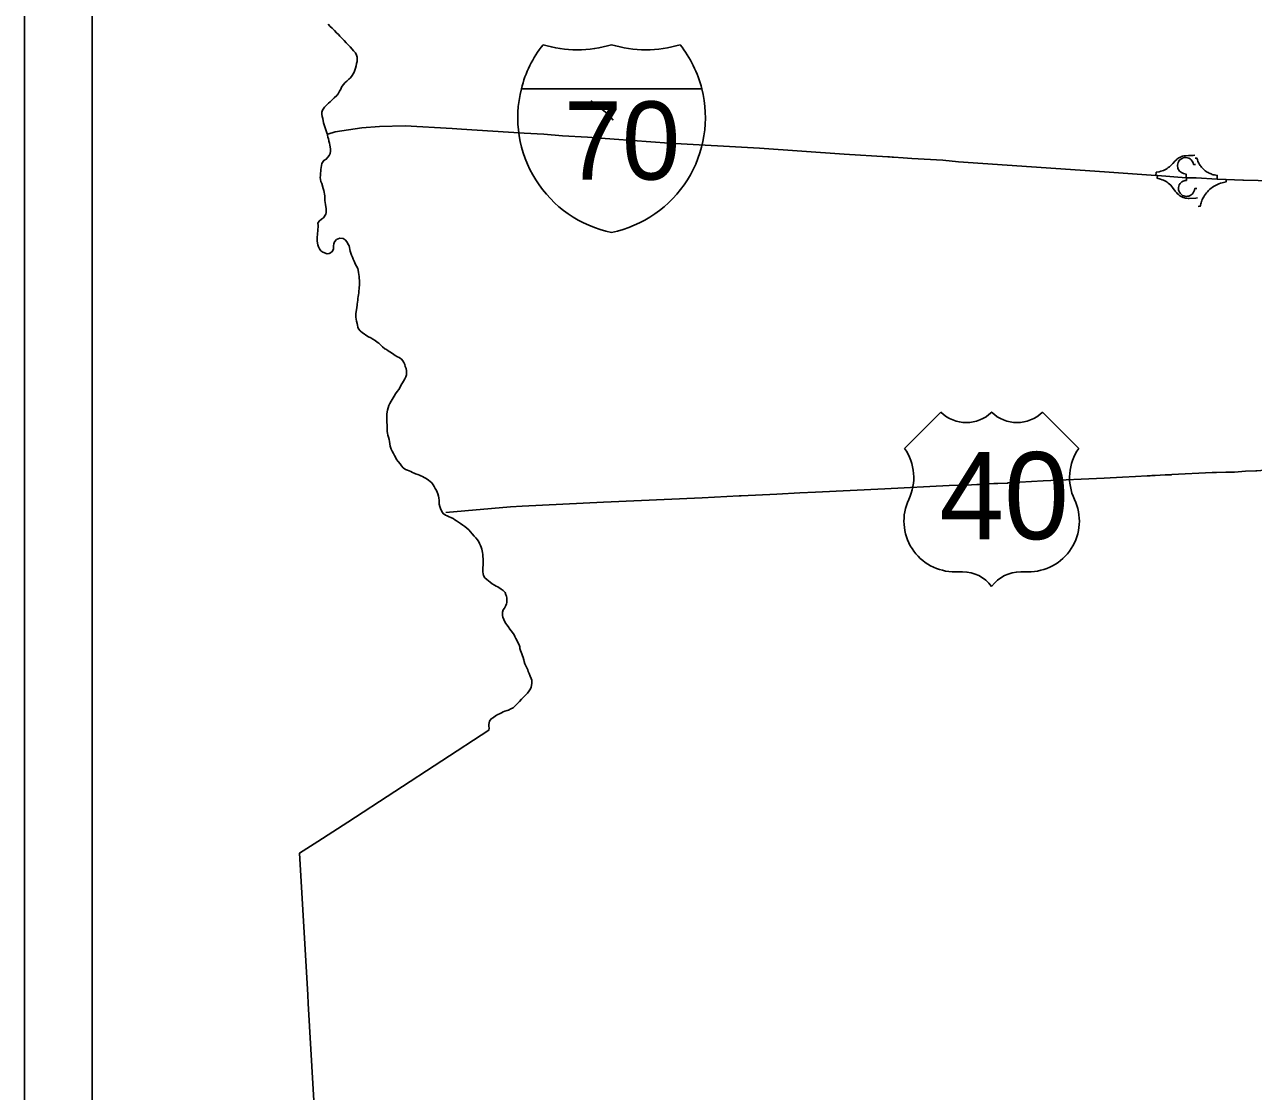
# Model space of a CAD drawing. Extents: x -7.1 to 34, y 0 to 22.
# Drawn here: x 2 to 3.818, y 16.034 to 17.612 of the extents above; entities that cross this region are included whole.
import ezdxf

# ---------------------------------------------------------------- set-up
doc = ezdxf.new("R2010")
doc.units = 0
for name, color, linetype in [('GM_X_County', 7, 'Continuous'), ('GM_X_County_Road', 7, 'Continuous'), ('GM_X_Interchange_Ramps', 7, 'Continuous'), ('GM_X_Interstate_Route', 7, 'Continuous'), ('GM_X_Interstate_Shield', 7, 'Continuous'), ('GM_X_US_Route', 7, 'Continuous'), ('GM_X_US_Shield', 7, 'Continuous'), ('SH_Data', 7, 'Continuous')]:
    doc.layers.add(name, color=color, linetype=linetype)

msp = doc.modelspace()

# ---------------------------------------------------------------- linework, layer by layer
at = {"layer": 'GM_X_County'}
msp.add_lwpolyline([(2.4304, 15.9776), (2.4197, 16.1634), (2.4189, 16.1766), (2.4068, 16.3861), (2.434, 16.4032), (2.478, 16.4318), (2.6868, 16.5679), (2.6875, 16.571), (2.687, 16.5738), (2.6869, 16.5762), (2.6873, 16.5787), (2.688, 16.5816), (2.6904, 16.5847), (2.6936, 16.5869), (2.6968, 16.589), (2.6999, 16.591), (2.7024, 16.5923), (2.7055, 16.5939), (2.7079, 16.5952), (2.7105, 16.596), (2.7137, 16.597), (2.716, 16.5978), (2.7195, 16.5994), (2.7228, 16.6013), (2.726, 16.6041), (2.7291, 16.6073), (2.7324, 16.6105), (2.7353, 16.6139), (2.7379, 16.6169), (2.7409, 16.6197), (2.7439, 16.623), (2.7466, 16.6263), (2.7485, 16.6293), (2.7494, 16.6316), (2.7501, 16.6342), (2.7504, 16.6374), (2.7506, 16.6398), (2.7503, 16.6422), (2.7495, 16.6447), (2.7479, 16.6479), (2.7467, 16.6517), (2.7452, 16.655), (2.7444, 16.6573), (2.7429, 16.6604), (2.7415, 16.6633), (2.7402, 16.666), (2.7392, 16.6694), (2.7386, 16.6722), (2.7377, 16.6754), (2.7366, 16.6779), (2.7356, 16.6808), (2.7344, 16.6836), (2.7336, 16.686), (2.7327, 16.6891), (2.7325, 16.6915), (2.7317, 16.6945), (2.7304, 16.697), (2.7288, 16.7001), (2.7268, 16.7039), (2.7255, 16.7064), (2.7241, 16.7092), (2.7217, 16.7125), (2.7199, 16.7151), (2.7181, 16.7175), (2.7152, 16.7213), (2.7135, 16.7237), (2.7119, 16.7261), (2.7104, 16.7285), (2.7089, 16.7317), (2.7077, 16.735), (2.7071, 16.7375), (2.7068, 16.7398), (2.707, 16.7427), (2.7082, 16.7462), (2.7099, 16.7487), (2.7121, 16.7524), (2.713, 16.7548), (2.7134, 16.7571), (2.7136, 16.7606), (2.7133, 16.7634), (2.7127, 16.7662), (2.7121, 16.7685), (2.7108, 16.7715), (2.708, 16.7746), (2.7051, 16.7767), (2.7002, 16.78), (2.6979, 16.7812), (2.695, 16.7828), (2.6919, 16.7847), (2.6887, 16.7869), (2.6862, 16.7888), (2.6839, 16.7908), (2.6811, 16.7936), (2.6789, 16.7967), (2.6782, 16.7995), (2.6779, 16.8024), (2.6779, 16.8054), (2.678, 16.8085), (2.6782, 16.8123), (2.6783, 16.8156), (2.6784, 16.8189), (2.6783, 16.8221), (2.678, 16.8245), (2.6777, 16.8279), (2.6774, 16.8309), (2.6763, 16.8357), (2.6754, 16.8386), (2.6745, 16.8411), (2.6729, 16.8444), (2.6718, 16.8467), (2.67, 16.8498), (2.6676, 16.8525), (2.6652, 16.8553), (2.662, 16.8584), (2.6597, 16.8616), (2.6572, 16.8644), (2.6543, 16.8671), (2.6512, 16.8692), (2.6481, 16.8713), (2.6448, 16.8737), (2.639, 16.8779), (2.6366, 16.8792), (2.6338, 16.881), (2.6306, 16.8827), (2.6281, 16.8839), (2.625, 16.8852), (2.6226, 16.8862), (2.6194, 16.8885), (2.6183, 16.8902), (2.6168, 16.8925), (2.6153, 16.8958), (2.6142, 16.899), (2.6134, 16.9026), (2.6132, 16.905), (2.6131, 16.908), (2.6129, 16.9117), (2.6124, 16.9141), (2.6114, 16.9175), (2.6105, 16.9202), (2.6093, 16.9225), (2.6076, 16.9255), (2.6059, 16.9286), (2.6047, 16.9309), (2.6023, 16.934), (2.5999, 16.9358), (2.5975, 16.9379), (2.5942, 16.9403), (2.591, 16.9421), (2.5886, 16.9433), (2.5863, 16.9444), (2.584, 16.9453), (2.5816, 16.9464), (2.5785, 16.9475), (2.5762, 16.9484), (2.5738, 16.9495), (2.5713, 16.9505), (2.5688, 16.9515), (2.5665, 16.9525), (2.5635, 16.9538), (2.5603, 16.9563), (2.5576, 16.959), (2.5554, 16.9621), (2.5527, 16.9653), (2.5504, 16.9686), (2.5487, 16.972), (2.5473, 16.9745), (2.546, 16.9772), (2.5437, 16.9808), (2.5422, 16.9839), (2.541, 16.9883), (2.5403, 16.9916), (2.5398, 16.9949), (2.5392, 16.9983), (2.5382, 17.0015), (2.5373, 17.0046), (2.5367, 17.0075), (2.5365, 17.0098), (2.5363, 17.0148), (2.5362, 17.0175), (2.5362, 17.02), (2.5359, 17.023), (2.5357, 17.0259), (2.5358, 17.0291), (2.5359, 17.0321), (2.5361, 17.0356), (2.5363, 17.0389), (2.5368, 17.0416), (2.5378, 17.0449), (2.5388, 17.0482), (2.5404, 17.0513), (2.5422, 17.0547), (2.5438, 17.0572), (2.5452, 17.0596), (2.5467, 17.0622), (2.5486, 17.0655), (2.5514, 17.0691), (2.5538, 17.0719), (2.5554, 17.0756), (2.5572, 17.0788), (2.559, 17.082), (2.5608, 17.0844), (2.5626, 17.0879), (2.5639, 17.0907), (2.5649, 17.094), (2.5651, 17.0968), (2.565, 17.0997), (2.5644, 17.1031), (2.5632, 17.1062), (2.5623, 17.1092), (2.5613, 17.1119), (2.5594, 17.1146), (2.5575, 17.1169), (2.5543, 17.1192), (2.5516, 17.1206), (2.5484, 17.1226), (2.5461, 17.124), (2.5429, 17.1261), (2.5405, 17.1278), (2.5378, 17.1295), (2.5353, 17.1312), (2.533, 17.1323), (2.5296, 17.1352), (2.5272, 17.1375), (2.524, 17.1404), (2.5216, 17.1422), (2.5186, 17.1445), (2.5153, 17.1463), (2.512, 17.1483), (2.5089, 17.1502), (2.505, 17.1523), (2.5022, 17.1543), (2.4999, 17.1558), (2.4965, 17.1588), (2.4941, 17.1619), (2.493, 17.1643), (2.4924, 17.1671), (2.4918, 17.1699), (2.4912, 17.1732), (2.4906, 17.1763), (2.4902, 17.1789), (2.4901, 17.1814), (2.4902, 17.184), (2.4906, 17.1873), (2.4911, 17.19), (2.4917, 17.1936), (2.492, 17.1966), (2.4922, 17.199), (2.4924, 17.2007), (2.4925, 17.2013), (2.4928, 17.204), (2.4932, 17.2065), (2.4936, 17.2095), (2.494, 17.2123), (2.4943, 17.2151), (2.4946, 17.2178), (2.495, 17.221), (2.4951, 17.2236), (2.4953, 17.226), (2.4954, 17.2285), (2.4956, 17.2309), (2.4955, 17.2336), (2.4952, 17.2365), (2.4949, 17.2392), (2.494, 17.2454), (2.4934, 17.2484), (2.4928, 17.2512), (2.4912, 17.2545), (2.4898, 17.257), (2.4887, 17.2594), (2.4875, 17.2618), (2.4863, 17.2648), (2.4852, 17.2678), (2.4838, 17.271), (2.4827, 17.2737), (2.4819, 17.2768), (2.4814, 17.2792), (2.4806, 17.2821), (2.48, 17.2845), (2.4784, 17.2878), (2.4771, 17.2901), (2.4741, 17.2935), (2.4712, 17.2956), (2.4663, 17.296), (2.4639, 17.2952), (2.4616, 17.2939), (2.4587, 17.2907), (2.4575, 17.2878), (2.457, 17.2844), (2.457, 17.282), (2.4569, 17.2796), (2.4552, 17.276), (2.4527, 17.2741), (2.4504, 17.2735), (2.4476, 17.273), (2.4413, 17.2752), (2.4384, 17.2773), (2.4361, 17.2803), (2.4347, 17.2833), (2.4336, 17.2862), (2.4333, 17.2888), (2.4328, 17.2921), (2.4328, 17.2946), (2.433, 17.2977), (2.4332, 17.3009), (2.4334, 17.3033), (2.4337, 17.3064), (2.434, 17.3096), (2.4343, 17.3119), (2.4345, 17.3148), (2.434, 17.318), (2.4359, 17.3213), (2.4391, 17.3241), (2.4422, 17.3261), (2.4456, 17.3316), (2.4461, 17.3341), (2.4461, 17.3366), (2.446, 17.3398), (2.4458, 17.3423), (2.4452, 17.3458), (2.4447, 17.3489), (2.4444, 17.3515), (2.4441, 17.3562), (2.444, 17.3585), (2.4438, 17.361), (2.4432, 17.3641), (2.4427, 17.3664), (2.4417, 17.3696), (2.4399, 17.3767), (2.4385, 17.3798), (2.4377, 17.3828), (2.4375, 17.3858), (2.4376, 17.3889), (2.4379, 17.392), (2.4382, 17.3951), (2.4385, 17.3974), (2.4388, 17.4004), (2.4391, 17.4035), (2.44, 17.4065), (2.4427, 17.4109), (2.4463, 17.4126), (2.4485, 17.4156), (2.4507, 17.4183), (2.452, 17.4213), (2.4525, 17.4246), (2.4525, 17.4278), (2.452, 17.4311), (2.4517, 17.4338), (2.4512, 17.4364), (2.4502, 17.4395), (2.45, 17.4405), (2.4494, 17.4429), (2.4488, 17.4456), (2.448, 17.4482), (2.4474, 17.4501), (2.4461, 17.4547), (2.445, 17.4575), (2.4443, 17.4606), (2.4433, 17.4636), (2.4423, 17.4664), (2.4413, 17.473), (2.4402, 17.476), (2.4399, 17.4792), (2.44, 17.4826), (2.4408, 17.4851), (2.4439, 17.4898), (2.4467, 17.4927), (2.4494, 17.4955), (2.4519, 17.4976), (2.4552, 17.5008), (2.458, 17.5036), (2.4617, 17.507), (2.4637, 17.5097), (2.466, 17.5133), (2.4677, 17.5164), (2.4689, 17.5195), (2.4711, 17.523), (2.4744, 17.5263), (2.4768, 17.5282), (2.4798, 17.531), (2.482, 17.5334), (2.4848, 17.5366), (2.4861, 17.539), (2.4874, 17.5414), (2.4886, 17.5445), (2.4895, 17.5474), (2.4906, 17.551), (2.4912, 17.5542), (2.4918, 17.5574), (2.4921, 17.5614), (2.4919, 17.5639), (2.4911, 17.5669), (2.4895, 17.5701), (2.4866, 17.573), (2.4847, 17.5755), (2.4815, 17.5788), (2.4786, 17.582), (2.4757, 17.5848), (2.4726, 17.5885), (2.4699, 17.5913), (2.4666, 17.5946), (2.4642, 17.5972), (2.4615, 17.5998), (2.4583, 17.6031), (2.4552, 17.6066), (2.4522, 17.6093), (2.4492, 17.6124)], dxfattribs=at)
at = {"layer": 'GM_X_County_Road'}
msp.add_lwpolyline([(2.8709, 17.4707), (2.8675, 17.4744), (2.8617, 17.4802), (2.8543, 17.4865), (2.8435, 17.495), (2.8377, 17.4993)], dxfattribs=at)
at = {"layer": 'GM_X_Interchange_Ramps'}
for points in [[(3.7313, 17.4186), (3.7287, 17.4184), (3.722, 17.4185), (3.7171, 17.418), (3.7152, 17.4176), (3.7131, 17.4171), (3.7116, 17.4166), (3.7101, 17.416), (3.7088, 17.4154), (3.7075, 17.4147), (3.7059, 17.4136), (3.7046, 17.4126), (3.7034, 17.4115), (3.7021, 17.4102), (3.6986, 17.4066), (3.6971, 17.4048), (3.6957, 17.4034), (3.6937, 17.4016), (3.692, 17.4003), (3.6904, 17.3992), (3.6886, 17.3981), (3.6869, 17.3971), (3.685, 17.3963), (3.6829, 17.3955), (3.6809, 17.3949), (3.6786, 17.3943), (3.6741, 17.3935), (3.6737, 17.3886)], [(3.7182, 17.3854), (3.7186, 17.3906), (3.7144, 17.3918), (3.7127, 17.3924), (3.7114, 17.393), (3.7099, 17.3941), (3.7087, 17.3952), (3.7077, 17.3965), (3.7069, 17.3977), (3.7063, 17.3992), (3.7059, 17.4007), (3.7056, 17.4024), (3.7056, 17.4041), (3.7059, 17.406), (3.7065, 17.4079), (3.7076, 17.4099), (3.7088, 17.4114), (3.7105, 17.4129), (3.7124, 17.414), (3.7139, 17.4146), (3.7158, 17.4151), (3.7182, 17.4152), (3.7204, 17.4148), (3.7225, 17.4141), (3.7243, 17.4131), (3.726, 17.4117), (3.7274, 17.4099), (3.7286, 17.4076), (3.7295, 17.4049), (3.732, 17.4051)], [(3.7641, 17.3834), (3.7644, 17.3887), (3.7601, 17.3895), (3.7584, 17.3899), (3.7569, 17.3903), (3.7553, 17.3909), (3.7538, 17.3915), (3.7526, 17.3921), (3.751, 17.3929), (3.7494, 17.3938), (3.7481, 17.3946), (3.7467, 17.3957), (3.7454, 17.3967), (3.7439, 17.398), (3.7426, 17.3993), (3.7412, 17.4009), (3.7401, 17.4024), (3.7391, 17.4037), (3.7382, 17.4051), (3.7372, 17.4069), (3.7364, 17.4085), (3.7358, 17.4099), (3.7351, 17.4117), (3.7342, 17.4144), (3.7315, 17.4143)], [(3.6759, 17.3885), (3.6757, 17.3846), (3.6803, 17.3834), (3.6827, 17.3825), (3.685, 17.3816), (3.6869, 17.3806), (3.6886, 17.3796), (3.6903, 17.3786), (3.6919, 17.3774), (3.6937, 17.376), (3.6955, 17.3743), (3.6969, 17.3727), (3.6983, 17.3711), (3.7024, 17.3656), (3.7039, 17.3635), (3.7053, 17.3619), (3.7069, 17.3604), (3.7084, 17.3591), (3.7101, 17.358), (3.712, 17.357), (3.714, 17.3561), (3.7158, 17.3555), (3.7175, 17.3552), (3.7191, 17.3549), (3.7212, 17.3547), (3.7231, 17.3547), (3.7328, 17.3553), (3.7351, 17.3554)], [(3.7341, 17.3696), (3.7313, 17.3695), (3.7306, 17.3672), (3.7299, 17.365), (3.7289, 17.3631), (3.7274, 17.3612), (3.7258, 17.3599), (3.7242, 17.359), (3.7225, 17.3583), (3.7205, 17.3579), (3.7183, 17.3578), (3.7164, 17.3581), (3.7148, 17.3585), (3.7131, 17.3593), (3.7118, 17.3602), (3.7104, 17.3614), (3.7094, 17.3627), (3.7084, 17.3642), (3.7077, 17.366), (3.7073, 17.3674), (3.7071, 17.369), (3.7072, 17.3708), (3.7075, 17.3727), (3.7083, 17.3747), (3.7094, 17.3766), (3.7106, 17.378), (3.7121, 17.3793), (3.714, 17.3804), (3.7155, 17.3809), (3.717, 17.3813), (3.7188, 17.3815), (3.7191, 17.3853)], [(3.7362, 17.343), (3.7392, 17.3432), (3.7396, 17.345), (3.7401, 17.3469), (3.7405, 17.3484), (3.7411, 17.35), (3.7417, 17.3514), (3.7423, 17.353), (3.7435, 17.3554), (3.7445, 17.3573), (3.7456, 17.359), (3.7469, 17.361), (3.7483, 17.3628), (3.75, 17.3647), (3.7517, 17.3665), (3.7536, 17.3684), (3.7552, 17.3697), (3.7571, 17.3711), (3.759, 17.3723), (3.7616, 17.3739), (3.7639, 17.3751), (3.7667, 17.3763), (3.7693, 17.3772), (3.7717, 17.3779), (3.7738, 17.3784), (3.7775, 17.3791), (3.7776, 17.3829)]]:
    msp.add_lwpolyline(points, dxfattribs=at)
at = {"layer": 'GM_X_Interstate_Route'}
for points in [[(2.4487, 17.45), (2.4596, 17.4532), (2.4987, 17.4592), (2.5253, 17.4614), (2.563, 17.4622), (2.6325, 17.4581), (2.6466, 17.457), (2.739, 17.4512), (2.768, 17.4498), (2.7959, 17.4476), (2.8327, 17.4455), (2.8723, 17.4424), (2.9535, 17.4366), (3.0873, 17.4293), (3.2127, 17.4203), (3.2773, 17.4163), (3.2797, 17.4161), (3.2833, 17.4159)], [(3.2833, 17.4159), (3.2857, 17.4157)], [(3.2857, 17.4157), (3.2997, 17.4149), (3.3127, 17.414)], [(3.3127, 17.414), (3.3583, 17.4112), (3.3817, 17.4088), (3.5976, 17.3939)], [(3.5976, 17.3939), (3.6737, 17.3886), (3.6759, 17.3885), (3.7182, 17.3854), (3.7191, 17.3853), (3.7323, 17.385)], [(3.7323, 17.385), (3.7332, 17.385), (3.7641, 17.3834), (3.7776, 17.3829), (3.8023, 17.3817)], [(3.8023, 17.3817), (3.8031, 17.3817), (3.8678, 17.3801), (3.8961, 17.3791)]]:
    msp.add_lwpolyline(points, dxfattribs=at)
at = {"layer": 'GM_X_Interstate_Shield'}
for p, q in [((2.7348, 17.5171), (3.0019, 17.5171)), ((3.0019, 17.5171), (2.7348, 17.5171)), ((3.0019, 17.5171), (2.7348, 17.5171))]:
    msp.add_line(p, q, dxfattribs=at)
for centre, start, end in [((2.9031, 17.4745), 141.669, 165.8066), ((2.8177, 17.7481), 253.0091, 286.9909), ((2.9191, 17.7481), 253.0091, 286.9909), ((2.8337, 17.4745), 14.1934, 38.331), ((2.9031, 17.4745), 165.8066, 258.463), ((2.8337, 17.4745), 281.537, 14.1934)]:
    msp.add_arc(centre, 0.1735, start, end, dxfattribs=at)
at = {"layer": 'GM_X_US_Route'}
for points in [[(3.624, 16.9424), (3.6434, 16.9433), (3.6605, 16.9442)], [(3.6605, 16.9442), (3.6654, 16.9445)], [(3.6654, 16.9445), (3.6678, 16.9446)], [(3.6678, 16.9446), (3.6714, 16.9448), (3.6727, 16.9448)], [(3.6727, 16.9448), (3.6873, 16.9456)], [(3.6873, 16.9456), (3.6965, 16.946), (3.6971, 16.9461)], [(3.6971, 16.9461), (3.7569, 16.9491), (3.7581, 16.9491)], [(3.7581, 16.9491), (3.7633, 16.9494), (3.777, 16.9496), (3.7777, 16.9496)], [(3.7777, 16.9496), (3.7801, 16.9497), (3.79, 16.95), (3.8062, 16.9512), (3.8217, 16.9517), (3.8228, 16.9518), (3.8288, 16.952), (3.8415, 16.9527), (3.846, 16.953), (3.8535, 16.9535), (3.8596, 16.9538), (3.8639, 16.954)], [(2.7359, 16.8995), (2.8563, 16.9056), (3.0025, 16.9119), (3.0569, 16.9149), (3.0602, 16.9149), (3.1127, 16.9174), (3.1467, 16.9191), (3.1701, 16.9202), (3.2727, 16.9252), (3.3677, 16.9299)], [(3.3677, 16.9299), (3.3932, 16.9305), (3.4011, 16.9311)], [(3.4011, 16.9311), (3.4086, 16.9315), (3.4124, 16.9317)], [(3.4124, 16.9317), (3.4172, 16.9319), (3.4258, 16.9323), (3.4337, 16.9328), (3.4396, 16.933), (3.4539, 16.9337), (3.4552, 16.9338)], [(3.4552, 16.9338), (3.507, 16.9368)], [(3.507, 16.9368), (3.5972, 16.9411)], [(3.5972, 16.9411), (3.624, 16.9424)], [(2.6231, 16.8903), (2.719, 16.8986), (2.7359, 16.8995)]]:
    msp.add_lwpolyline(points, dxfattribs=at)
at = {"layer": 'GM_X_US_Shield'}
for p, q in [((3.3555, 17.0385), (3.3018, 16.9848)), ((3.5595, 16.9848), (3.5058, 17.0385)), ((3.377, 16.8023), (3.3877, 16.8023)), ((3.4736, 16.8023), (3.4844, 16.8023))]:
    msp.add_line(p, q, dxfattribs=at)
for centre, radius, start, end in [((3.3931, 17.0769), 0.0537, 225.573, 314.427), ((3.4682, 17.0769), 0.0537, 225.573, 314.427), ((3.2402, 16.9417), 0.0752, 334.5471, 35.0009), ((3.6211, 16.9417), 0.0752, 144.9991, 205.4529), ((3.3761, 16.8775), 0.0752, 154.8319, 270.6383), ((3.4852, 16.8775), 0.0752, 269.3617, 25.1681), ((3.3877, 16.7486), 0.0537, 36.8699, 90), ((3.4736, 16.7486), 0.0537, 90, 143.1301)]:
    msp.add_arc(centre, radius, start, end, dxfattribs=at)
at = {"layer": 'SH_Data'}
for p, q in [((2, 21), (2, 14)), ((2.1, 20.9), (2.1, 14.1))]:
    msp.add_line(p, q, dxfattribs=at)

# ---------------------------------------------------------------- texts
at = {"layer": 'GM_X_Interstate_Shield'}
msp.add_text('70', height=0.11569, dxfattribs=at).set_placement((2.7978, 17.3826))
at = {"layer": 'GM_X_US_Shield'}
msp.add_text('40', height=0.12885, dxfattribs=at).set_placement((3.3533, 16.8506))

doc.saveas('drawing.dxf')
